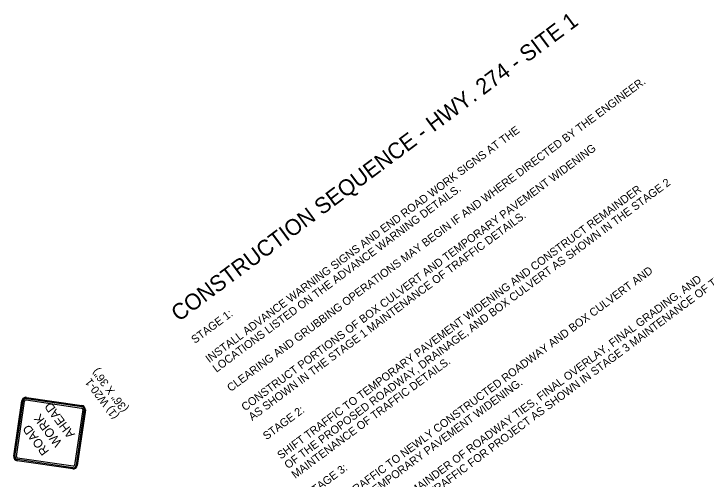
# Model space of a CAD drawing. Extents: x -238 to 1487, y -1123 to 446.
# Drawn here: x -145 to 374, y -424 to -75 of the extents above; entities that cross this region are included whole.
import ezdxf

# ---------------------------------------------------------------- set-up
doc = ezdxf.new("R2010")
doc.units = 0
doc.layers.add('P_TC_Signs_Temporary', color=7, linetype='Continuous')
doc.layers.add('R_Border Prem', color=7, linetype='Continuous')

msp = doc.modelspace()

# ---------------------------------------------------------------- linework, layer by layer
at = {"layer": 'P_TC_Signs_Temporary'}
for p, q in [((-135.95, -362.5), (-94.4, -368.57)), ((-145.43, -406.59), (-139.36, -365.03)), ((-144.6, -406.71), (-138.53, -365.15)), ((-143.45, -406.88), (-137.38, -365.32)), ((-136.24, -364.48), (-94.68, -370.55)), ((-136.08, -363.32), (-94.52, -369.39)), ((-93.84, -371.68), (-99.91, -413.24)), ((-92.69, -371.85), (-98.76, -413.41)), ((-91.86, -371.97), (-97.93, -413.53)), ((-101.33, -416.07), (-142.89, -409.99)), ((-101.21, -415.24), (-142.77, -409.17)), ((-101.04, -414.09), (-142.6, -408.02))]:
    msp.add_line(p, q, dxfattribs=at)
for centre, radius, start, end in [((-136.39, -365.47), 3, 81.6891, 171.6891), ((-136.39, -365.47), 2.17, 81.6891, 171.6891), ((-136.39, -365.47), 1, 81.6891, 171.6891), ((-94.83, -371.54), 1, 351.6891, 81.6891), ((-94.83, -371.54), 2.17, 351.6891, 81.6891), ((-94.83, -371.54), 3, 351.6891, 81.6891), ((-142.46, -407.03), 3, 171.6891, 261.6891), ((-142.46, -407.03), 2.17, 171.6891, 261.6891), ((-142.46, -407.03), 1, 171.6891, 261.6891), ((-100.9, -413.1), 3, 261.6891, 351.6891), ((-100.9, -413.1), 2.17, 261.6891, 351.6891), ((-100.9, -413.1), 1, 261.6891, 351.6891)]:
    msp.add_arc(centre, radius, start, end, dxfattribs=at)

# ---------------------------------------------------------------- texts
for s, p in [(' AHEAD ', (-97.86, -392.13)), ('WORK', (-109.03, -396.52)), (' ROAD ', (-117.23, -404.88))]:
    msp.add_text(s, height=6.667, rotation=126.6891, dxfattribs=at).set_placement(p)
at = {"layer": 'R_Border Prem'}
for s, height, rotation, p in [('CONSTRUCTION SEQUENCE - HWY. 274 - SITE 1', 12, 36.6341, (-21.84, -306.17)), ('CLEARING AND GRUBBING OPERATIONS MAY BEGIN IF AND WHERE DIRECTED BY THE ENGINEER.', 6, 36.6341, (17.15, -358.6)), ('INSTALL ADVANCE WARNING SIGNS AND END ROAD WORK SIGNS AT THE', 6, 36.6341, (1.04, -336.93)), ('CONSTRUCT PORTIONS OF BOX CULVERT AND TEMPORARY PAVEMENT WIDENING', 6, 36.6341, (27.89, -373.04)), ('OF THE PROPOSED ROADWAY, DRAINAGE, AND BOX CULVERT AS SHOWN IN THE STAGE 2', 6, 36.6341, (60.11, -416.38)), ('LOCATIONS LISTED ON THE ADVANCE WARNING DETAILS.', 6, 36.6341, (6.41, -344.15)), ('SHIFT TRAFFIC TO TEMPORARY PAVEMENT WIDENING AND CONSTRUCT REMAINDER ', 6, 36.6341, (54.74, -409.15)), ('AS SHOWN IN THE STAGE 1 MAINTENANCE OF TRAFFIC DETAILS. ', 6, 36.6341, (33.26, -380.26)), ('DRAINAGE UNDER TRAFFIC FOR PROJECT AS SHOWN IN STAGE 3 MAINTENANCE OF TRAFFIC', 6, 36.6341, (108.44, -481.38)), ('SHIFT TRAFFIC TO NEWLY CONSTRUCTED ROADWAY AND BOX CULVERT AND ', 6, 36.6341, (86.96, -452.49)), ('CONSTRUCT REMAINDER OF ROADWAY TIES, FINAL OVERLAY, FINAL GRADING, AND ', 6, 36.6341, (103.07, -474.15)), ('STAGE 1:', 6, 36.6341, (-9.7, -322.49)), ('MAINTENANCE OF TRAFFIC DETAILS.', 6, 36.6341, (65.48, -423.6)), ('(36" X 36")', 6, 126.6891, (-59.43, -371.03)), ('(1) W20-1', 6, 126.6891, (-66.43, -376.24)), ('REMOVE TEMPORARY PAVEMENT WIDENING. ', 6, 36.6341, (92.33, -459.71)), ('STAGE 2:', 6, 36.6341, (44, -394.71)), ('STAGE 3:', 6, 36.6341, (76.22, -438.04))]:
    msp.add_text(s, height=height, rotation=rotation, dxfattribs=at).set_placement(p)

doc.saveas('drawing.dxf')
